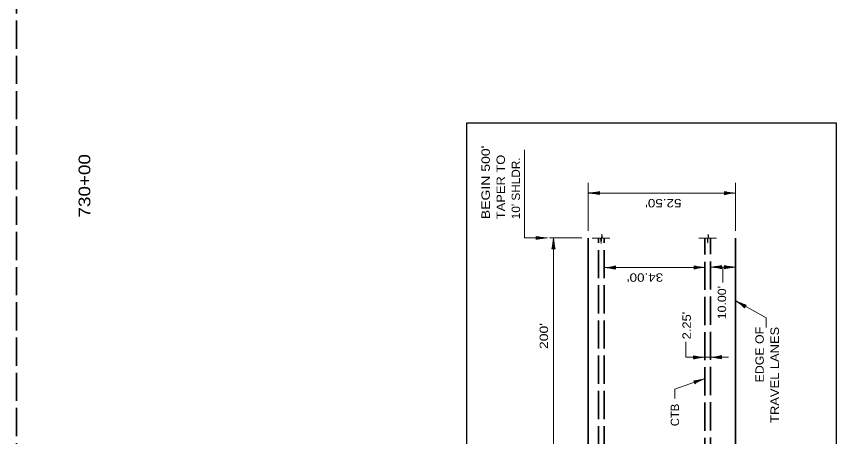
# Model space of a CAD drawing. Extents: x 2363427 to 2368559, y 6957299 to 6980140.
# Drawn here: x 2366756 to 2367735, y 6973549 to 6974050 of the extents above; entities that cross this region are included whole.
import ezdxf
from ezdxf.enums import TextEntityAlignment as Align

# ---------------------------------------------------------------- set-up
doc = ezdxf.new("R2010")
doc.units = 0
doc.header["$LTSCALE"] = 5.6
doc.linetypes.add('LONG_DASHED', pattern=[7.5, 6, -1.5])
doc.layers.add('44', color=7, linetype='Continuous', lineweight=13)
doc.layers.add('8', color=7, linetype='Continuous', lineweight=13)

msp = doc.modelspace()

# ---------------------------------------------------------------- linework, layer by layer
at = {"layer": '44', "linetype": 'LONG_DASHED', "lineweight": 35}
msp.add_line((2366755.923, 6973255.766), (2366755.923, 6977094.896), dxfattribs=at)
at = {"layer": '8'}
for p, q in [((2367438.326, 6973851.791), (2367438.326, 6973794.47)), ((2367614.113, 6973851.788), (2367614.113, 6973794.469)), ((2367438.326, 6973839.728), (2367614.112, 6973839.728)), ((2367451.636, 6973839.78), (2367439.074, 6973839.792)), ((2367451.637, 6973839.281), (2367443.028, 6973839.29)), ((2367451.637, 6973840.28), (2367444.29, 6973840.288)), ((2367451.636, 6973838.78), (2367446.776, 6973838.785)), ((2367451.64, 6973840.78), (2367447.363, 6973840.786)), ((2367451.637, 6973838.28), (2367449.256, 6973838.282)), ((2367451.638, 6973841.28), (2367450.054, 6973841.282)), ((2367451.639, 6973841.632), (2367451.634, 6973837.801)), ((2367600.824, 6973837.664), (2367600.78, 6973841.494)), ((2367600.785, 6973841.014), (2367603.165, 6973841.041)), ((2367600.79, 6973840.514), (2367605.652, 6973840.568)), ((2367600.797, 6973840.014), (2367609.404, 6973840.11)), ((2367600.8, 6973839.516), (2367613.364, 6973839.655)), ((2367600.81, 6973839.015), (2367608.156, 6973839.096)), ((2367600.812, 6973838.515), (2367605.088, 6973838.562)), ((2367600.82, 6973838.015), (2367602.404, 6973838.032)), ((2367376.248, 6973784.128), (2367376.206, 6973787.96)), ((2367376.21, 6973787.48), (2367378.592, 6973787.506)), ((2367376.216, 6973786.98), (2367381.077, 6973787.034)), ((2367376.222, 6973786.48), (2367384.832, 6973786.574)), ((2367376.228, 6973785.98), (2367388.79, 6973786.12)), ((2367376.234, 6973785.48), (2367383.582, 6973785.561)), ((2367376.238, 6973784.98), (2367380.515, 6973785.026)), ((2367376.244, 6973784.48), (2367377.828, 6973784.497)), ((2367392.203, 6973786.1), (2367430.586, 6973786.1)), ((2367396.397, 6973773.14), (2367396.406, 6973781.75)), ((2367396.896, 6973773.14), (2367396.908, 6973785.703)), ((2367396.933, 6973500.427), (2367396.932, 6973786.1)), ((2367397.396, 6973773.14), (2367397.402, 6973780.488)), ((2367398.748, 6973773.138), (2367394.916, 6973773.142)), ((2367395.395, 6973773.14), (2367395.398, 6973775.522)), ((2367395.896, 6973773.141), (2367395.901, 6973778.002)), ((2367397.896, 6973773.138), (2367397.901, 6973777.414)), ((2367398.396, 6973773.139), (2367398.398, 6973774.723)), ((2367457.076, 6973750.987), (2367577.272, 6973750.987)), ((2367470.838, 6973750.838), (2367458.276, 6973750.85)), ((2367470.837, 6973750.339), (2367462.228, 6973750.348)), ((2367470.837, 6973751.338), (2367463.49, 6973751.346)), ((2367470.838, 6973749.838), (2367465.976, 6973749.843)), ((2367470.84, 6973751.838), (2367466.563, 6973751.844)), ((2367470.837, 6973749.338), (2367468.456, 6973749.34)), ((2367470.839, 6973752.338), (2367469.254, 6973752.34)), ((2367470.839, 6973752.689), (2367470.836, 6973748.859)), ((2367564.73, 6973748.996), (2367564.688, 6973752.826)), ((2367564.692, 6973752.346), (2367567.074, 6973752.373)), ((2367564.698, 6973751.846), (2367569.559, 6973751.9)), ((2367564.704, 6973751.346), (2367573.313, 6973751.441)), ((2367564.709, 6973750.848), (2367577.272, 6973750.987)), ((2367564.716, 6973750.346), (2367572.064, 6973750.428)), ((2367564.72, 6973749.846), (2367568.997, 6973749.893)), ((2367564.726, 6973749.346), (2367566.31, 6973749.364)), ((2367584.023, 6973751.35), (2367614.022, 6973751.35)), ((2367597.335, 6973751.401), (2367584.772, 6973751.414)), ((2367597.334, 6973750.902), (2367588.724, 6973750.911)), ((2367597.334, 6973751.901), (2367589.986, 6973751.908)), ((2367597.334, 6973750.4), (2367592.472, 6973750.406)), ((2367597.336, 6973752.401), (2367593.06, 6973752.406)), ((2367597.334, 6973749.9), (2367594.952, 6973749.903)), ((2367597.336, 6973752.901), (2367595.752, 6973752.904)), ((2367597.336, 6973753.252), (2367597.333, 6973749.422)), ((2367599.008, 6973732.839), (2367599.006, 6973751.35)), ((2367600.734, 6973749.286), (2367600.692, 6973753.117)), ((2367600.696, 6973752.637), (2367603.078, 6973752.664)), ((2367600.702, 6973752.137), (2367605.563, 6973752.191)), ((2367600.708, 6973751.638), (2367609.317, 6973751.732)), ((2367600.713, 6973751.138), (2367613.276, 6973751.278)), ((2367600.72, 6973750.638), (2367608.068, 6973750.719)), ((2367600.724, 6973750.138), (2367605.001, 6973750.184)), ((2367600.73, 6973749.638), (2367602.314, 6973749.655)), ((2367625.898, 6973704.53), (2367615.038, 6973710.847)), ((2367625.647, 6973704.1), (2367618.204, 6973708.427)), ((2367626.148, 6973704.963), (2367619.796, 6973708.658)), ((2367625.395, 6973703.666), (2367621.192, 6973706.11)), ((2367626.4, 6973705.394), (2367622.704, 6973707.545)), ((2367625.144, 6973703.234), (2367623.086, 6973704.431)), ((2367626.828, 6973706.13), (2367624.902, 6973702.819)), ((2367626.651, 6973705.828), (2367625.283, 6973706.624)), ((2367554.619, 6973643.821), (2367554.62, 6973662.249)), ((2367554.619, 6973643.821), (2367605.642, 6973643.82)), ((2367563.814, 6973641.757), (2367563.773, 6973645.588)), ((2367563.778, 6973645.108), (2367566.158, 6973645.134)), ((2367563.782, 6973644.608), (2367568.644, 6973644.662)), ((2367563.79, 6973644.108), (2367572.397, 6973644.202)), ((2367563.794, 6973643.608), (2367576.358, 6973643.748)), ((2367563.8, 6973643.108), (2367571.149, 6973643.19)), ((2367563.805, 6973642.608), (2367568.081, 6973642.654)), ((2367563.81, 6973642.108), (2367565.394, 6973642.126)), ((2367597.166, 6973643.872), (2367584.603, 6973643.885)), ((2367597.164, 6973643.373), (2367588.556, 6973643.382)), ((2367597.164, 6973644.372), (2367589.818, 6973644.38)), ((2367597.166, 6973642.872), (2367592.303, 6973642.877)), ((2367597.168, 6973644.872), (2367592.89, 6973644.878)), ((2367597.165, 6973642.372), (2367594.784, 6973642.374)), ((2367597.166, 6973645.372), (2367595.584, 6973645.375)), ((2367597.166, 6973645.724), (2367597.164, 6973641.893)), ((2367577.406, 6973618.288), (2367541.756, 6973605.812)), ((2367565.392, 6973612.244), (2367564.176, 6973615.876)), ((2367564.327, 6973615.421), (2367566.584, 6973616.177)), ((2367564.486, 6973614.946), (2367569.096, 6973616.491)), ((2367564.644, 6973614.472), (2367572.809, 6973617.206)), ((2367564.803, 6973613.999), (2367576.718, 6973617.988)), ((2367564.964, 6973613.525), (2367571.93, 6973615.858)), ((2367565.122, 6973613.05), (2367569.176, 6973614.408)), ((2367565.28, 6973612.576), (2367566.784, 6973613.079)), ((2367541.756, 6973605.812), (2367541.756, 6973594.574))]:
    msp.add_line(p, q, dxfattribs=at)
at = {"layer": '8', "lineweight": 35}
for p, q in [((2367438.326, 6973234.129), (2367438.326, 6973786.03)), ((2367614.044, 6972934.175), (2367614.044, 6973786.028))]:
    msp.add_line(p, q, dxfattribs=at)
at = {"layer": '8', "linetype": 'LONG_DASHED', "lineweight": 35}
for p, q in [((2367450.326, 6973234.13), (2367450.326, 6973785.814)), ((2367457.077, 6973234.13), (2367457.076, 6973785.676)), ((2367577.272, 6973220.2), (2367577.273, 6973786.028)), ((2367584.022, 6973220.62), (2367584.022, 6973786.028))]:
    msp.add_line(p, q, dxfattribs=at)
at = {"layer": '8', "lineweight": 25}
msp.add_lwpolyline([(2367734.622, 6972753.759), (2367734.622, 6973923.111), (2367292.864, 6973923.111), (2367292.864, 6972753.759)], close=True, dxfattribs=at)
at = {"layer": '8'}
for points in [[(2367362.252, 6973891.252), (2367362.252, 6973786.18), (2367389.218, 6973786.18)], [(2367443.144, 6973785.814), (2367453.056, 6973785.814), (2367453.882, 6973779.622), (2367454.295, 6973790.49), (2367455.258, 6973785.675), (2367464.207, 6973785.676)], [(2367570.091, 6973786.028), (2367580.004, 6973786.028), (2367580.829, 6973779.836), (2367581.242, 6973790.706), (2367582.206, 6973785.89), (2367591.154, 6973785.89)], [(2367614.357, 6973711.166), (2367650.708, 6973690.675), (2367650.708, 6973679.436)]]:
    msp.add_lwpolyline(points, dxfattribs=at)
for centre, start, end in [((2367434.815, 6973911.856), 272.78627, 283.47232), ((2367434.671, 6973767.609), 76.41311, 87.09916), ((2367616.89, 6973911.887), 257.1087, 267.79475), ((2367618.497, 6973767.649), 93.48186, 104.16791), ((2367392.315, 6973858.351), 257.1087, 267.79475), ((2367393.922, 6973714.113), 93.48186, 104.16791), ((2367324.723, 6973790.107), 346.41311, 357.09916), ((2367468.97, 6973789.963), 182.78627, 193.47232), ((2367454.016, 6973822.914), 272.78627, 283.47232), ((2367453.872, 6973678.667), 76.41311, 87.09916), ((2367580.797, 6973823.219), 257.1087, 267.79475), ((2367582.404, 6973678.98), 93.48186, 104.16791), ((2367580.368, 6973679.229), 76.41311, 87.09916), ((2367580.513, 6973823.476), 272.78627, 283.47232), ((2367616.801, 6973823.509), 257.1087, 267.79475), ((2367618.408, 6973679.271), 93.48186, 104.16791), ((2367575.004, 6973650.619), 46.29152, 56.97757), ((2367647.517, 6973775.315), 242.66469, 253.35074), ((2367579.882, 6973715.98), 257.1087, 267.79475), ((2367581.489, 6973571.742), 93.48186, 104.16791), ((2367580.199, 6973571.701), 76.41311, 87.09916), ((2367580.344, 6973715.948), 272.78627, 283.47232), ((2367557.896, 6973687.815), 274.98766, 285.67371), ((2367603.708, 6973551.036), 111.36082, 122.04688)]:
    msp.add_arc(centre, 72.212, start, end, dxfattribs=at)

# ---------------------------------------------------------------- texts
at = {"layer": '44', "width": 1.2}
msp.add_text('730+00', height=14, rotation=90, dxfattribs=at).set_placement((2366844.15, 6973848.315), align=Align.CENTER)
at = {"layer": '8'}
for s, rotation, width, p in [("BEGIN 500'", 90, 1.25, (2367320.847, 6973808.46)), ('TAPER TO', 90, 1.15, (2367338.847, 6973808.46)), ("10' SHLDR.", 90, 1.05, (2367356.847, 6973808.46)), ("52.50'", 180, 1.2, (2367549.553, 6973832.634)), ("34.00'", 180, 1.2, (2367527.742, 6973743.892)), ("10.00'", 90, 1.1, (2367602.764, 6973689.123)), ("2.25'", 90, 1.15, (2367560.683, 6973665.184)), ("200'", 90, 1.25, (2367390.295, 6973653.556))]:
    msp.add_text(s, height=10, rotation=rotation, dxfattribs=dict(at, width=width)).set_placement(p)
for s, width, p in [('EDGE OF', 1.1, (2367647.723, 6973680.071)), ('TRAVEL LANES', 1.15, (2367665.724, 6973680.072))]:
    msp.add_text(s, height=10, rotation=90, dxfattribs=dict(at, width=width)).set_placement(p, align=Align.RIGHT)
msp.add_text('CTB', height=10, rotation=90, dxfattribs=at).set_placement((2367546.66, 6973588.361), align=Align.RIGHT)

doc.saveas('drawing.dxf')
